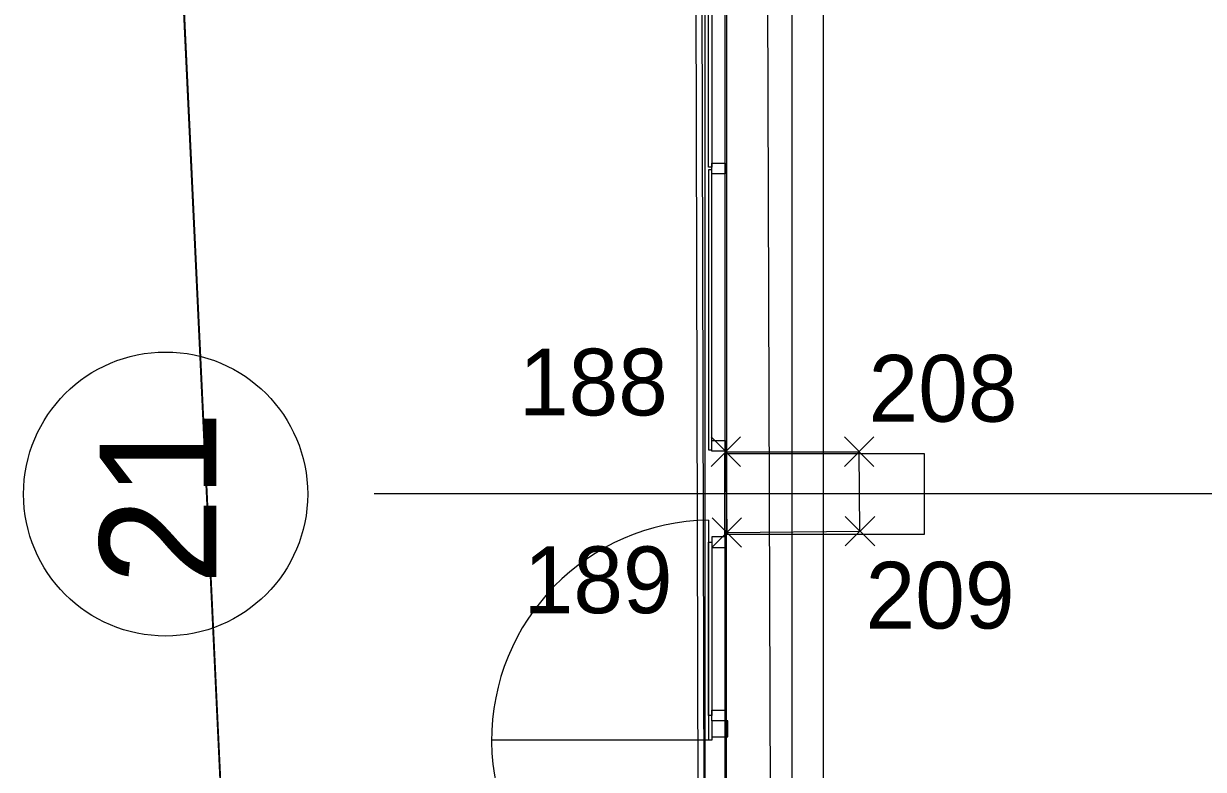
# Model space of a CAD drawing. Extents: x -264205 to -263659, y -1242401 to -1242060.
# Drawn here: x -263914.15 to -263905.31, y -1242218.95 to -1242213.36 of the extents above; entities that cross this region are included whole.
import ezdxf

# ---------------------------------------------------------------- set-up
doc = ezdxf.new("R2010")
doc.units = 0
for name, color, linetype in [('BOD_CISLO', 7, 'Continuous'), ('BOD_SYMBOL', 7, 'Continuous'), ('KFA_SO_10-1_BETONOVE_STLPY', 7, 'Continuous'), ('KFA_SO_10-1_PLACHTY', 7, 'Continuous'), ('KFA_SO_10-1_STRECHY', 7, 'Continuous'), ('KFA_SO_10-1_TRIBUNA_A_OBVOD', 7, 'Continuous'), ('OBRUBNIKY_KOMUNIKACIE_PROJEKT', 7, 'Continuous'), ('OSI_STAVBY_KFA', 7, 'Continuous'), ('SITUACIA_DSP_2D', 7, 'Continuous')]:
    doc.layers.add(name, color=color, linetype=linetype)

msp = doc.modelspace()

# ---------------------------------------------------------------- linework, layer by layer
at = {"layer": 'BOD_SYMBOL'}
for p, q in [((-263908.9975, -1242216.6755), (-263908.7765, -1242216.4545)), ((-263908.7765, -1242216.6755), (-263908.9975, -1242216.4545)), ((-263907.9985, -1242216.6755), (-263907.7775, -1242216.4545)), ((-263907.7775, -1242216.6755), (-263907.9985, -1242216.4545)), ((-263908.9905, -1242217.2815), (-263908.7695, -1242217.0605)), ((-263908.7695, -1242217.2815), (-263908.9905, -1242217.0605)), ((-263907.9925, -1242217.2715), (-263907.7715, -1242217.0505)), ((-263907.7715, -1242217.2715), (-263907.9925, -1242217.0505))]:
    msp.add_line(p, q, dxfattribs=at)
at = {"layer": 'KFA_SO_10-1_BETONOVE_STLPY'}
for p, q in [((-263908.8872, -1242216.565), (-263908.8802, -1242217.1706)), ((-263908.8872, -1242216.565), (-263907.8882, -1242216.565)), ((-263907.8823, -1242217.1613), (-263907.8882, -1242216.565)), ((-263908.8802, -1242217.1706), (-263907.8823, -1242217.1613))]:
    msp.add_line(p, q, dxfattribs=at)
at = {"layer": 'KFA_SO_10-1_PLACHTY'}
for p, q in [((-263908.632, -1242196.778), (-263908.53, -1242226.78)), ((-263909.149, -1242196.844), (-263909.08, -1242226.989)), ((-263909.031, -1242226.94), (-263909.097, -1242199.693))]:
    msp.add_line(p, q, dxfattribs=at)
msp.add_lwpolyline([(-263912.238, -1242228.302), (-263912.237, -1242228.313), (-263913.727, -1242196.804), (-263913.722, -1242196.8)], close=True, dxfattribs=at)
at = {"layer": 'KFA_SO_10-1_STRECHY'}
msp.add_line((-263908.157, -1242227.179), (-263908.136, -1242101.59), dxfattribs=at)
at = {"layer": 'KFA_SO_10-1_TRIBUNA_A_OBVOD'}
msp.add_lwpolyline([(-263908.6566, -1242227.5451), (-263908.8875, -1242226.9875), (-263908.8713, -1242203.3778)], dxfattribs=at)
at = {"layer": 'OBRUBNIKY_KOMUNIKACIE_PROJEKT'}
msp.add_line((-263909.0427, -1242227.3822), (-263909.0427, -1242196.3327), dxfattribs=at)
at = {"layer": 'OSI_STAVBY_KFA'}
for p, q in [((-263908.3928, -1242083.2372), (-263908.3928, -1242246.7072)), ((-263792.6528, -1242216.8822), (-263911.5228, -1242216.8822))]:
    msp.add_line(p, q, dxfattribs=at)
msp.add_circle((-263913.0851, -1242216.8825), 1.0643, dxfattribs=at)
at = {"layer": 'SITUACIA_DSP_2D'}
for p, q in [((-263909.0428, -1242227.3822), (-263909.0428, -1242196.3327)), ((-263908.8928, -1242226.9954), (-263908.8928, -1242203.3322)), ((-263909.0177, -1242214.4323), (-263909.0177, -1242212.3323)), ((-263908.9927, -1242212.3323), (-263908.9927, -1242214.4323)), ((-263908.9927, -1242214.4423), (-263908.9927, -1242214.4023)), ((-263908.9927, -1242214.4023), (-263908.8927, -1242214.4023)), ((-263908.8927, -1242214.4023), (-263908.8927, -1242214.4823)), ((-263908.9927, -1242214.4323), (-263909.0177, -1242214.4323)), ((-263909.0177, -1242214.4523), (-263909.0177, -1242216.5523)), ((-263908.9927, -1242214.4523), (-263909.0177, -1242214.4523)), ((-263908.9927, -1242214.4823), (-263908.9927, -1242214.4423)), ((-263908.9927, -1242216.5523), (-263908.9927, -1242214.4523)), ((-263908.8927, -1242214.4823), (-263908.9927, -1242214.4823)), ((-263908.9927, -1242216.5223), (-263908.9927, -1242216.4823)), ((-263908.9927, -1242216.4823), (-263908.8927, -1242216.4823)), ((-263908.9927, -1242216.5623), (-263908.9927, -1242216.5223)), ((-263908.8927, -1242216.4823), (-263908.8927, -1242216.5623)), ((-263909.0177, -1242216.5523), (-263908.9927, -1242216.5523)), ((-263908.8927, -1242216.5623), (-263908.9927, -1242216.5623)), ((-263907.3977, -1242216.5823), (-263908.8977, -1242216.5823)), ((-263908.8977, -1242216.5823), (-263908.8977, -1242217.1823)), ((-263907.3977, -1242217.1823), (-263907.3977, -1242216.5823)), ((-263909.0177, -1242217.0775), (-263909.0177, -1242218.7273)), ((-263908.8927, -1242217.2023), (-263908.9927, -1242217.2023)), ((-263908.9927, -1242217.2023), (-263908.9927, -1242217.2423)), ((-263908.8977, -1242217.1823), (-263907.3977, -1242217.1823)), ((-263908.8927, -1242217.2823), (-263908.8927, -1242217.2023)), ((-263909.0177, -1242218.5423), (-263909.0177, -1242217.2423)), ((-263909.0177, -1242217.2423), (-263908.9927, -1242217.2423)), ((-263908.9927, -1242217.2423), (-263908.9927, -1242218.5423)), ((-263908.9927, -1242217.2423), (-263908.9927, -1242217.2823)), ((-263908.9927, -1242217.2823), (-263908.8927, -1242217.2823)), ((-263908.9927, -1242218.5423), (-263909.0177, -1242218.5423)), ((-263908.9927, -1242218.5423), (-263908.9927, -1242218.5023)), ((-263908.9927, -1242218.5023), (-263908.8927, -1242218.5023)), ((-263908.9927, -1242218.5823), (-263908.9927, -1242218.5423)), ((-263908.8927, -1242218.5023), (-263908.8927, -1242218.5823)), ((-263908.8927, -1242218.5823), (-263908.9927, -1242218.5823)), ((-263908.8727, -1242218.5823), (-263908.9927, -1242218.5823)), ((-263908.9927, -1242218.5823), (-263908.9927, -1242218.7023)), ((-263908.8727, -1242218.7023), (-263908.8727, -1242218.5823)), ((-263908.9927, -1242218.7273), (-263910.6427, -1242218.7273)), ((-263908.9927, -1242218.7023), (-263908.9927, -1242218.7273)), ((-263908.9927, -1242218.7023), (-263908.8727, -1242218.7023))]:
    msp.add_line(p, q, dxfattribs=at)
msp.add_arc((-263908.9927, -1242218.7273), 1.65, 90.86815, 270, dxfattribs=at)

# ---------------------------------------------------------------- texts
at = {"layer": 'BOD_CISLO'}
for s, p in [('188', (-263910.4375, -1242216.2933)), ('208', (-263907.8175, -1242216.3403)), ('189', (-263910.4023, -1242217.7753)), ('209', (-263907.8397, -1242217.8904))]:
    msp.add_text(s, height=0.5, dxfattribs=at).set_placement(p)
at = {"layer": 'OSI_STAVBY_KFA'}
msp.add_text('21', height=0.875, rotation=90, dxfattribs=at).set_placement((-263912.7045, -1242217.5623))

doc.saveas('drawing.dxf')
